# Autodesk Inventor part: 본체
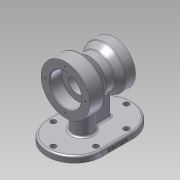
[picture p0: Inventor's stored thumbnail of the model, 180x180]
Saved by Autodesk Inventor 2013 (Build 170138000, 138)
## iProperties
Created: 2020-01
Part Number: 본체
Material: 알루미늄 6061
Document SubType Name: Modeling
Designer: Administrator
Density: 2.71 g/cm^3
Mass: 941.582 g
Surface Area: 654.888 cm^2
Volume: 347.447 cm^3
Author: Administrator
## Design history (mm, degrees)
sketch "스케치1"
  geometry: L1 (-40, 0)-(40, 0); L2 (-40, 0)-(-40, 40); L3 (-40, 40)-(-16, 40); L4 (-16, 40)-(-1.103, 27.5); L5 (-1.103, 27.5)-(13.289, 27.5); L6 (24, 35)-(40, 35); L7 (40, 35)-(40, 0); L8 (24, 35)-(13.289, 27.5); 2 further points
  constraints: 16 end point, 3 parallel, 2 perpendicular, 1 coincident, 1 horizontal, 1 midpoint
  dimensions: "d0" = 80 distance of L1.start L1.end; "d2" = 24 distance of L2.end L3.end; "d6" = 55 diameter of L5 L1; "d7" = 70 diameter of L6 L1; "d8" = 80 diameter of L3 L1; "d9" = 16 distance of L6.start L6.end; "d10" = 35 deg angle of L5 L8; "d11" = 40 deg angle of L5 L4
revolve "회전1" sketch "스케치1" stored, may be unused: angle "d12" = 90 deg
hole "구멍1" diameter "d15" = 32; stored, may be unused: countersink angle "d19" = 90 deg, drill point angle "d21" = 118 deg; dims "d13" = 10, "d14" = 10, "d16" = 6, "d17" = 52, "d18" = 20, "d20" = 8
hole "구멍2" diameter "d24" = 40; stored, may be unused: countersink angle "d28" = 90 deg, drill point angle "d30" = 0 deg; dims "d22" = 10, "d23" = 10, "d25" = 6, "d26" = 52, "d27" = 20, "d29" = 17
fillet "모깎기1" dims "d31" = 0.3
sketch "스케치2"
  geometry: L1 (-70, -70)-(70, -70); L2 (70, -70)-(70, -80); L3 (70, -80)-(-70, -80); L4 (-70, -80)-(-70, -70); 2 further points
  constraints: 8 end point, 2 parallel, 1 horizontal, 1 midpoint, 1 perpendicular, 1 vertical alignment
  dimensions: "d33" = 80 distance from line of L3 point (0, 0); "d34" = 10 distance between parallel lines of L3 L1; "d35" = 140 distance between parallel lines of L4 L2
extrude "돌출1" join sketch "스케치2" stored distance "d36" = 90; taper "d37" = 0 deg
fillet "모깎기2" dims "d38" = 45
sketch "스케치3"
  geometry: L1 (0, 0)-(50, 0) reference; L2 (50, -90)-(0, -90) reference; L3 (28.199, -40)-(55, -40); L4 (55, -40)-(55, -50); L5 (55, -50)-(28.199, -50); L6 (65, -80)-(65, -10) reference; L7 (-15, -85)-(-15, -5) reference; A1 r 45 centre (50, -45) between (50, -90) and (50, 0) reference; A2 r 45 centre (0, -45) between (0, 0) and (0, -90) reference; A3 r 16 centre (13, -45) between (28.199, -40) and (28.199, -50); A4 r 45 centre (0, -45) between (0, 0) and (0, -90); 2 further points
  constraints: 8 end point, 5 point on circle, 2 centre point, 2 parallel, 1 coincident, 1 horizontal alignment, 1 perpendicular
  dimensions: "d41" = 32 diameter of A3; "d42" = 5 distance from line of A1.centre L3; "d43" = 10 distance between parallel lines of L5 L3; "d45" = 58 distance of A3.centre point (-45, -45); "d88" = 10 distance between parallel lines of L6 L4
extrude "돌출2" join sketch "스케치3" stored distance "d46" = 90; taper "d47" = 0 deg
sketch "스케치4"
  geometry: L1 (0, 0)-(50, 0) reference; L2 (50, -90)-(0, -90) reference; L3 (50, -80)-(0, -80); L4 (0, -10)-(50, -10); A1 r 45 centre (50, -45) between (50, -90) and (50, 0) reference; A2 r 45 centre (0, -45) between (0, 0) and (0, -90) reference; A3 r 35 centre (50, -45) between (50, -80) and (50, -10); A4 r 35 centre (0, -45) between (0, -10) and (0, -80); A5 r 45 centre (50, -45) between (50, -90) and (50, 0) reference; 8 further points
  constraints: 6 point on circle, 5 coincident, 4 end point, 2 centre point, 3 other
  dimensions: "d48" = 10 distance between parallel lines of L1 L4
hole "구멍3" sketch "스케치4" at (-35, -45), (85, -45), (50, -10), (50, -80), (0, -80), (0, -10) diameter "d49" = 9; stored, may be unused: countersink angle "d53" = 90 deg, drill point angle "d55" = 0 deg; dims "d50" = 6, "d51" = 52, "d52" = 20, "d54" = 17
sketch "스케치5" dims "d56" = 66
  geometry: C1 r 26 at (0, 0) reference; C2 r 40 at (0, 0) reference; 2 further points
  constraints: 2 vertical alignment, 1 coincident, 2 other
hole "구멍4" sketch "스케치5" at (0, 33) diameter "d58" = 3.242; stored, may be unused: countersink angle "d62" = 90 deg, drill point angle "d64" = 118 deg; dims "d59" = 9, "d60" = 52, "d61" = 20, "d63" = 11
sketch "스케치6" dims "d68" = 55
  geometry: C1 r 20 at (0, 0) reference; C2 r 35 at (0, 0) reference; 2 further points
  constraints: 2 vertical alignment, 1 coincident, 2 other
hole "구멍5" sketch "스케치6" at (0, 27.5) diameter "d70" = 3.242; stored, may be unused: countersink angle "d74" = 90 deg, drill point angle "d76" = 118 deg; dims "d71" = 9, "d72" = 52, "d73" = 20, "d75" = 11
fillet "모깎기3" dims "d80" = 3
chamfer "모따기1" distance "d81" = 1; stored, may be unused: second distance "d82" = 2, angle "d83" = 45 deg
fillet "모깎기5" dims "d85" = 3
fillet "모깎기6" dims "d86" = 3
fillet "모깎기7" dims "d87" = 3
fillet "모깎기8" dims "d89" = 3
sketch "스케치7"
  geometry: L1 (-25, -80)-(25, -80) reference; L2 (-70, -73)-(-70, -80) reference; 2 further points
  constraints: 1 other
  dimensions: "d90" = 4 distance from line of L1 point (0, -76); "d91" = 70 distance from line of point (0, -76) L2
feature "엠보싱1" sketch "스케치7" dims "d0" = 80, "d2" = 24, "d6" = 55, "d7" = 70, "d8" = 80, "d9" = 16, "d10" = 35 deg, "d11" = 40 deg, "d31" = 0.3, "d92" = 0.5, "d93" = 0
node "솔리드1"
pattern_circular "원형 패턴1" dims angle "d66" = 360 deg
pattern_circular "원형 패턴2" dims angle "d78" = 360 deg
